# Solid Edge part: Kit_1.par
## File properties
Sűrűség: 0,000 kg/m^3
Pontosság: 0,990
Author: bmolnar
Last saved by: bmolnar
Revision: 76
Username: bmolnar
Dokumentum tartalom típus: 0
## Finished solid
Body 1: solid body, 48 faces, 65 edges, 55 vertices.
  Faces by surface: cone 16, cylinder 15, plane 12, torus 5
  Edges by curve: circle 51, line 14
Bounding box of the edges (mm; curved faces can reach further): 85.500 x 85.350 x 18.200, from (-42.75, -40.85, 88.15) to (42.75, 44.5, 106.35).
Cylindrical faces by radius (mm): R1.5 x2, R3 x4, R10.3 x1, R10.95 x1, R11.5 x1, R12.4 x1, R12.5 x1, R22 x1, R37.5 x1, R40.85 x1, R42.75 x1
Conical faces (half-angle, radius in mm at the cone's reference point): 3 deg R12.45 x1, 7 deg R11.7695 x1, 14 deg R10.15 x1, 14 deg R10.557 x1, 17 deg R10.15 x1, 23 deg R10.9211 x1, 42.5 deg R10.137 x1, 45 deg R11.2 x1, 45 deg R11.65 x1, 45 deg R21.25 x1, 45 deg R40.75 x2, 60 deg R26.6072 x1, 84 deg R10.512 x1, 85 deg R12.1625 x1, 87 deg R10.2157 x1
Toroidal faces (ring radius, tube radius in mm): R10.9008 r0.225 x1, R11.3914 r0.325 x1, R12.2 r0.2 x1, R22.8 r0.8 x1, R31.2144 r0.8 x1
Planar faces by outward normal: +z 7, -z 3, oblique 2
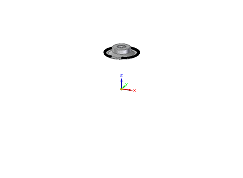
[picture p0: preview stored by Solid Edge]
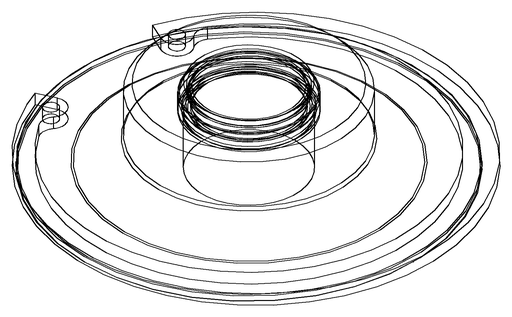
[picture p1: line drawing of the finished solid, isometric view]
